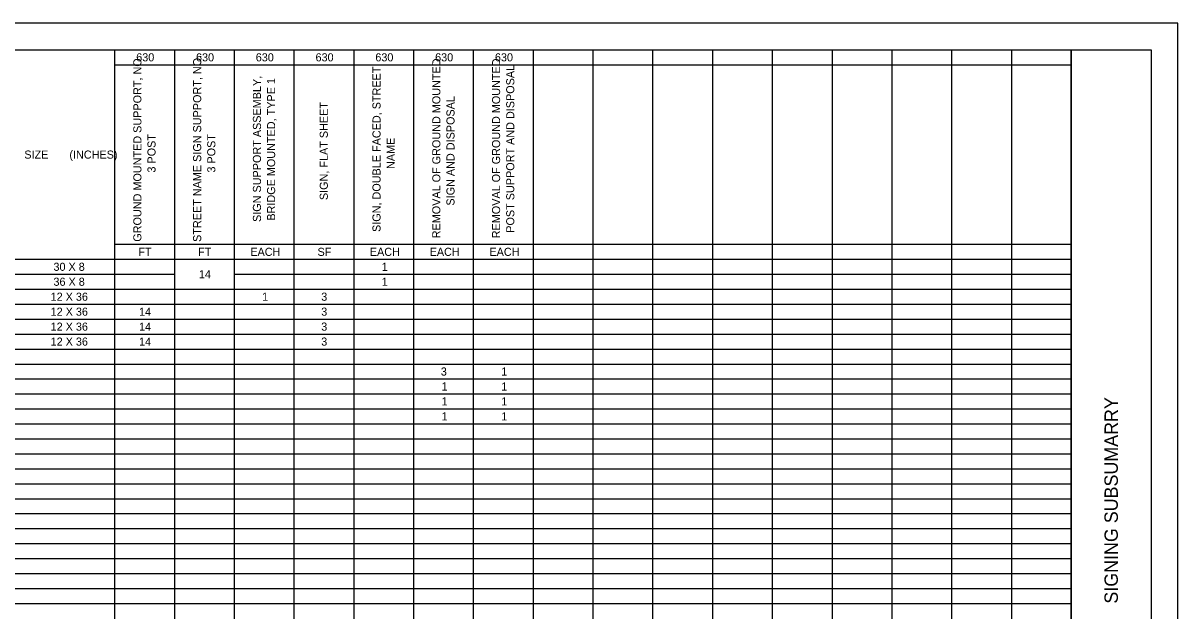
# Model space of a CAD drawing. Extents: x 0 to 34, y 0 to 22.
# Drawn here: x 12.37 to 34, y 11 to 22 of the extents above; entities that cross this region are included whole.
import ezdxf

# ---------------------------------------------------------------- set-up
doc = ezdxf.new("R2010")
doc.units = 0
for name, color, linetype in [('SH_Border', 7, 'Continuous'), ('SH_Cut_Line', 7, 'Continuous'), ('SH_Data', 7, 'Continuous'), ('SH_Text', 7, 'Continuous')]:
    doc.layers.add(name, color=color, linetype=linetype)

msp = doc.modelspace()

# ---------------------------------------------------------------- linework, layer by layer
at = {"layer": 'SH_Border'}
msp.add_line((32, 0.5), (32, 21.5), dxfattribs=at)
msp.add_lwpolyline([(1.5, 21.5), (33.5, 21.5), (33.5, 0.5), (1.5, 0.5)], close=True, dxfattribs=at)
at = {"layer": 'SH_Cut_Line'}
msp.add_lwpolyline([(0, 0), (34, 0), (34, 22), (0, 22)], close=True, dxfattribs=at)
at = {"layer": 'SH_Text'}
for p, q in [((1.5, 21.5), (32, 21.5)), ((14.082, 21.5), (14.082, 0.5)), ((15.202, 21.5), (15.202, 0.5)), ((16.322, 21.5), (16.322, 0.5)), ((17.442, 21.5), (17.442, 0.5)), ((18.562, 21.5), (18.562, 0.5)), ((19.681, 21.5), (19.681, 0.5)), ((20.801, 21.5), (20.801, 0.5)), ((21.921, 21.5), (21.921, 0.5)), ((23.041, 21.5), (23.041, 0.5)), ((24.161, 21.5), (24.161, 0.5)), ((25.281, 21.5), (25.281, 0.5)), ((26.401, 21.5), (26.401, 0.5)), ((27.521, 21.5), (27.521, 0.5)), ((28.64, 21.5), (28.64, 0.5)), ((29.76, 21.5), (29.76, 0.5)), ((30.88, 21.5), (30.88, 0.5)), ((32, 21.5), (32, 0.5)), ((14.082, 21.22), (32, 21.22)), ((14.082, 17.86), (32, 17.86)), ((1.5, 17.58), (32, 17.58)), ((10.591, 17.3), (15.202, 17.3)), ((16.322, 17.3), (32, 17.3)), ((1.5, 17.02), (32, 17.02)), ((1.5, 16.74), (32, 16.74)), ((1.5, 16.46), (32, 16.46)), ((1.5, 16.18), (32, 16.18)), ((1.5, 15.9), (32, 15.9)), ((1.5, 15.62), (32, 15.62)), ((1.5, 15.34), (32, 15.34)), ((1.5, 15.06), (32, 15.06)), ((1.5, 14.78), (32, 14.78)), ((1.5, 14.5), (32, 14.5)), ((1.5, 14.22), (32, 14.22)), ((1.5, 13.94), (32, 13.94)), ((1.5, 13.66), (32, 13.66)), ((1.5, 13.38), (32, 13.38)), ((1.5, 13.1), (32, 13.1)), ((1.5, 12.82), (32, 12.82)), ((1.5, 12.54), (32, 12.54)), ((1.5, 12.26), (32, 12.26)), ((1.5, 11.98), (32, 11.98)), ((1.5, 11.7), (32, 11.7)), ((1.5, 11.42), (32, 11.42)), ((1.5, 11.14), (32, 11.14))]:
    msp.add_line(p, q, dxfattribs=at)

# ---------------------------------------------------------------- texts
at = {"layer": 'SH_Data'}
msp.add_text('SIGNING SUBSUMARRY', height=0.25, rotation=90, dxfattribs=at).set_placement((32.875, 11.136))
at = {"layer": 'SH_Text'}
for s, height, p in [('630', 0.1515, (14.488, 21.284)), ('630', 0.1515, (15.608, 21.284)), ('630', 0.1515, (16.727, 21.284)), ('630', 0.1515, (17.847, 21.284)), ('630', 0.1515, (18.967, 21.284)), ('630', 0.1515, (20.087, 21.284)), ('630', 0.1515, (21.207, 21.284)), ('SIZE       (INCHES)', 0.15153, (12.392, 19.464)), ('FT', 0.1515, (14.528, 17.644)), ('FT', 0.1515, (15.647, 17.644)), ('EACH', 0.1515, (16.625, 17.644)), ('SF', 0.1515, (17.884, 17.644)), ('EACH', 0.1515, (18.864, 17.644)), ('EACH', 0.1515, (19.984, 17.644)), ('EACH', 0.1515, (21.104, 17.644)), ('30 X 8', 0.1515, (12.938, 17.364)), ('14', 0.1515, (15.661, 17.224)), ('1', 0.152, (19.086, 17.364)), ('36 X 8', 0.1515, (12.938, 17.084)), ('1', 0.152, (19.086, 17.084)), ('12 X 36', 0.1515, (12.885, 16.804)), ('1', 0.152, (16.846, 16.804)), ('3', 0.152, (17.953, 16.804)), ('12 X 36', 0.1515, (12.885, 16.524)), ('14', 0.1515, (14.541, 16.524)), ('3', 0.152, (17.953, 16.524)), ('12 X 36', 0.1515, (12.885, 16.244)), ('14', 0.1515, (14.541, 16.244)), ('3', 0.152, (17.953, 16.244)), ('12 X 36', 0.1515, (12.885, 15.964)), ('14', 0.1515, (14.541, 15.964)), ('3', 0.152, (17.953, 15.964)), ('3', 0.152, (20.193, 15.404)), ('1', 0.152, (21.326, 15.404)), ('1', 0.152, (20.206, 15.124)), ('1', 0.152, (21.326, 15.124)), ('1', 0.152, (20.206, 14.844)), ('1', 0.152, (21.326, 14.844)), ('1', 0.152, (20.206, 14.564)), ('1', 0.152, (21.326, 14.564))]:
    msp.add_text(s, height=height, dxfattribs=at).set_placement(p)
for s, height, p in [('GROUND MOUNTED SUPPORT, NO. ', 0.15151, (14.585, 17.909)), ('STREET NAME SIGN SUPPORT, NO. ', 0.15151, (15.705, 17.905)), ('REMOVAL OF GROUND MOUNTED ', 0.15151, (20.185, 17.973)), ('REMOVAL OF GROUND MOUNTED ', 0.15151, (21.304, 17.973)), ('POST SUPPORT AND DISPOSAL', 0.15151, (21.57, 18.077)), ('SIGN SUPPORT ASSEMBLY, ', 0.15151, (16.825, 18.278)), ('SIGN, DOUBLE FACED, STREET ', 0.15151, (19.065, 18.091)), ('BRIDGE MOUNTED, TYPE 1', 0.15151, (17.09, 18.303)), ('SIGN AND DISPOSAL', 0.15151, (20.45, 18.585)), ('SIGN, FLAT SHEET', 0.15151, (18.077, 18.688)), ('3 POST', 0.1515, (14.85, 19.203)), ('3 POST', 0.1515, (15.97, 19.203)), ('NAME', 0.1515, (19.33, 19.27))]:
    msp.add_text(s, height=height, rotation=90, dxfattribs=at).set_placement(p)

doc.saveas('drawing.dxf')
